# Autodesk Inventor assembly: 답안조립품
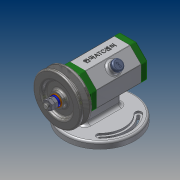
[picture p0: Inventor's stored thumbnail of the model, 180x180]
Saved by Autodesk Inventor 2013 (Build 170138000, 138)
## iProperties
Created: 2017-06
Part Number: 답안조립품
Document SubType Name: Assembly
Designer: Windows7
Author: Windows7
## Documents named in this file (14)
- C:\Users\Windows7\Desktop\470608V1025\답안조립품.iam
- C:\Users\Windows7\Desktop\470608V1025\본체.ipt
- C:\Users\Windows7\Desktop\470608V1025\베어링 15 x 32 x 9.ipt
- C:\Users\Windows7\Desktop\470608V1025\축.ipt
- C:\Users\Windows7\Desktop\470608V1025\키 3 x 3 x 12.ipt
- C:\Users\Windows7\Desktop\470608V1025\앞커버.ipt
- C:\Users\Windows7\Desktop\470608V1025\볼트 M4 x 12.ipt
- C:\Users\Windows7\Desktop\470608V1025\뒤커버.ipt
- C:\Users\Windows7\Desktop\470608V1025\오일 실 15 25 7.ipt
- C:\Users\Windows7\Desktop\470608V1025\V벨트풀리.ipt
- C:\Users\Windows7\Desktop\470608V1025\와셔 8x17.ipt
- C:\Users\Windows7\Desktop\470608V1025\스프링와셔 8.ipt
- C:\Users\Windows7\Desktop\470608V1025\너트 M 8.ipt
- C:\Users\Windows7\Desktop\470608V1025\고무캡.ipt
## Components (2 placed, 2 different names)
1. V벨트풀리:1
2. 고무캡:1
